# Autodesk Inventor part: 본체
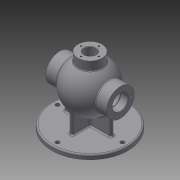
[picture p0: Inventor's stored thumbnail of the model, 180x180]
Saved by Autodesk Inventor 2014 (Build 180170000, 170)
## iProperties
Created: 2020-08
Part Number: 본체
Material: Generic
Document SubType Name: Modeling
Designer: kh
Density: 1 g/cm^3
Appearance: Default
Author: kh
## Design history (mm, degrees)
sketch "Sketch1"
  geometry: C1 r 85 at (0, 0); 1 further point
  constraints: 1 centre point, 1 coincident
  dimensions: "d0" = 170 diameter of C1
extrude "Extrusion1" new body sketch "Sketch1" distance "d1" = 10; taper "d2" = 0 deg
workplane "Work Plane1"
sketch "Sketch9"
  geometry: L1 (85, 10)-(-85, 10) reference; L2 (-85, 0)-(85, 0) reference; L3 (-76.651, 85)-(83.599, 85); L4 (-68, 116)-(-42.988, 116); L5 (42.988, 116)-(68, 116); L6 (-68, 102.5)-(-39.278, 102.5); L7 (39.278, 102.5)-(68, 102.5); L8 (68, 102.5)-(68, 116); L9 (-68, 102.5)-(-68, 116); L10 (0, 0)-(0, 85); A1 r 53 centre (0, 85) between (42.988, 116) and (-42.988, 116); A2 r 43 centre (0, 85) between (39.278, 102.5) and (-39.278, 102.5)
  constraints: 16 end point, 4 point on circle, 2 centre point, 2 coincident, 2 collinear, 2 parallel, 2 point on line, 2 vertical, 1 horizontal, 1 perpendicular, 1 other
  dimensions: "d72" = 85 distance from line of L2 L3.end; "d73" = 35 diameter of L6 L3; "d74" = 62 diameter of L4 L3; "d75" = 35 diameter of L7 L3; "d76" = 53 radius of A1; "d77" = 43 radius of A2; "d78" = 136 distance between parallel lines of L8 L9
revolve "Revolution2" sketch "Sketch9" stored, may be unused: angle "d79" = 90 deg
sketch "Sketch10"
  geometry: L1 (0, 0)-(0, 43); L2 (0, 43)-(-4, 43); L3 (-4, 43)-(-4, -43); L4 (-4, -43)-(4, -43); L5 (4, -43)-(4, 43); L6 (4, 43)-(0, 43); L7 (0, 0)-(-54, 0); L8 (-54, 0)-(-54, 4); L9 (-54, 4)-(50, 4); L10 (50, 4)-(50, -4); L11 (50, -4)-(-54, -4); L12 (-54, -4)-(-54, 0); C1 r 85 at (0, 0) reference; 1 further point
  constraints: 24 end point, 7 parallel, 2 perpendicular, 1 vertical
  dimensions: "d80" = 43 distance of L1.start L1.end; "d81" = 4 distance of L1.end L2.end; "d82" = 86 distance of L2.end L3.end; "d83" = 8 distance of L3.end L4.end; "d84" = 86 distance of L4.end L5.end; "d85" = 54 distance of L1.start L7.end; "d86" = 4 distance of L7.end L8.end; "d87" = 104 distance of L8.end L9.end; "d88" = 8 distance of L9.end L10.end; "d89" = 104 distance of L10.end L11.end
extrude "Extrusion7" join sketch "Sketch10" stored distance "d90" = 20; taper "d91" = 0 deg
workplane "Work Plane2"
sketch "Sketch11"
  geometry: C1 r 27 at (0, 0); 1 further point
  constraints: 1 centre point, 1 coincident
  dimensions: "d93" = 54 diameter of C1
extrude "Extrusion8" join sketch "Sketch11" stored distance "d94" = 20; taper "d95" = 0 deg
sketch "Sketch12" dims "d96" = 48
  geometry: L1 (0, 0)-(24, 0); C1 r 17.5 at (0, 0) reference; C2 r 31 at (0, 0) reference; 2 further points
  constraints: 2 coincident, 2 end point, 1 horizontal, 1 horizontal alignment, 2 other
hole "Hole1" sketch "Sketch12" at (24, 0) diameter "d97" = 3.459; stored, may be unused: countersink angle "d101" = 90 deg, drill point angle "d103" = 118 deg; dims "d98" = 12, "d99" = 4, "d100" = 2, "d102" = 15
pattern_circular "Circular Pattern1" dims angle "d105" = 360 deg
sketch "Sketch13" dims "d107" = 48
  geometry: L1 (0, 0)-(-24, 0); C1 r 31 at (0, 0) reference; C2 r 17.5 at (0, 0) reference; 2 further points
  constraints: 2 coincident, 2 end point, 1 horizontal, 1 horizontal alignment, 2 other
hole "Hole2" sketch "Sketch13" at (-24, 0) diameter "d108" = 3.459; stored, may be unused: countersink angle "d112" = 90 deg, drill point angle "d114" = 118 deg; dims "d109" = 12, "d110" = 4, "d111" = 2, "d113" = 15
pattern_circular "Circular Pattern2" dims angle "d116" = 360 deg
sketch "Sketch14"
  geometry: C1 r 27 at (0, 0) reference; C2 r 13 at (0, 0); 1 further point
  constraints: 1 centre point, 1 coincident
  dimensions: "d118" = 26 diameter of C2
extrude "Extrusion9" cut sketch "Sketch14" stored distance "d119" = 20; taper "d120" = 0 deg
sketch "Sketch15" dims "d121" = 40
  geometry: L1 (0, 0)-(0, 20); C1 r 13 at (0, 0) reference; C2 r 27 at (0, 0) reference; 2 further points
  constraints: 2 coincident, 2 end point, 1 vertical, 1 vertical alignment, 2 other
hole "Hole3" sketch "Sketch15" at (0, 20) diameter "d122" = 3.459; stored, may be unused: countersink angle "d126" = 90 deg, drill point angle "d128" = 118 deg; dims "d123" = 12, "d124" = 4, "d125" = 2, "d127" = 15
pattern_circular "Circular Pattern3" dims angle "d130" = 360 deg
sketch "Sketch16"
  geometry: L1 (0, 72.5)-(0, -72.5); L2 (-72.5, 0)-(72.5, 0); C1 r 85 at (0, 0) reference; A1 r 72.5 centre (0, 0) between (0, 72.5) and (0, -72.5); 7 further points
  constraints: 5 coincident, 4 end point, 4 midpoint, 4 point on circle, 1 centre point, 1 perpendicular, 1 vertical
  dimensions: "d132" = 145 diameter of A1
hole "Hole4" sketch "Sketch16" at (0, 72.5), (72.5, 0), (0, -72.5), (-72.5, 0) diameter "d133" = 9; stored, may be unused: countersink angle "d137" = 90 deg, drill point angle "d139" = 118 deg; dims "d134" = 12, "d135" = 4, "d136" = 2, "d138" = 15
sketch "Sketch17"
  geometry: L1 (-68, 67.5)-(-68, 102.5) reference; L2 (68, 67.5)-(68, 102.5) reference; L3 (-68, 85)-(68, 85); L4 (-39.278, 102.5)-(-68, 102.5) reference; L5 (-39.278, 67.5)-(-68, 67.5) reference; L6 (-52, 85)-(-52, 85); L7 (-52, 85)-(-52, 103.5); L8 (-52, 103.5)-(-50.25, 103.5); L9 (-50.25, 103.5)-(-50.25, 85); L10 (-52, 85)-(-50.25, 85); 1 further point
  constraints: 12 end point, 4 point on line, 3 perpendicular, 2 collinear, 2 midpoint
  dimensions: "d143" = 16 distance between parallel lines of L7 L1; "d144" = 37 diameter of L8 L3; "d145" = 1.75 distance of L7.end L8.end
revolve "Revolution3" sketch "Sketch17" stored, may be unused: angle "d146" = 90 deg
chamfer "Chamfer1" distance "d147" = 1; stored, may be unused: second distance "d148" = 2, angle "d149" = 45 deg
fillet "Fillet1" dims "d150" = 3
fillet "Fillet2" dims "d151" = 3
fillet "Fillet3" dims "d152" = 3
fillet "Fillet4" dims "d153" = 3
fillet "Fillet5" dims "d154" = 3
body "Solid1"
node "Projected Loop7"
node "Projected Loop8"
node "Projected Loop9"
node "Projected Loop10"
node "Projected Loop11"
node "Projected Loop12"
node "Projected Loop13"
